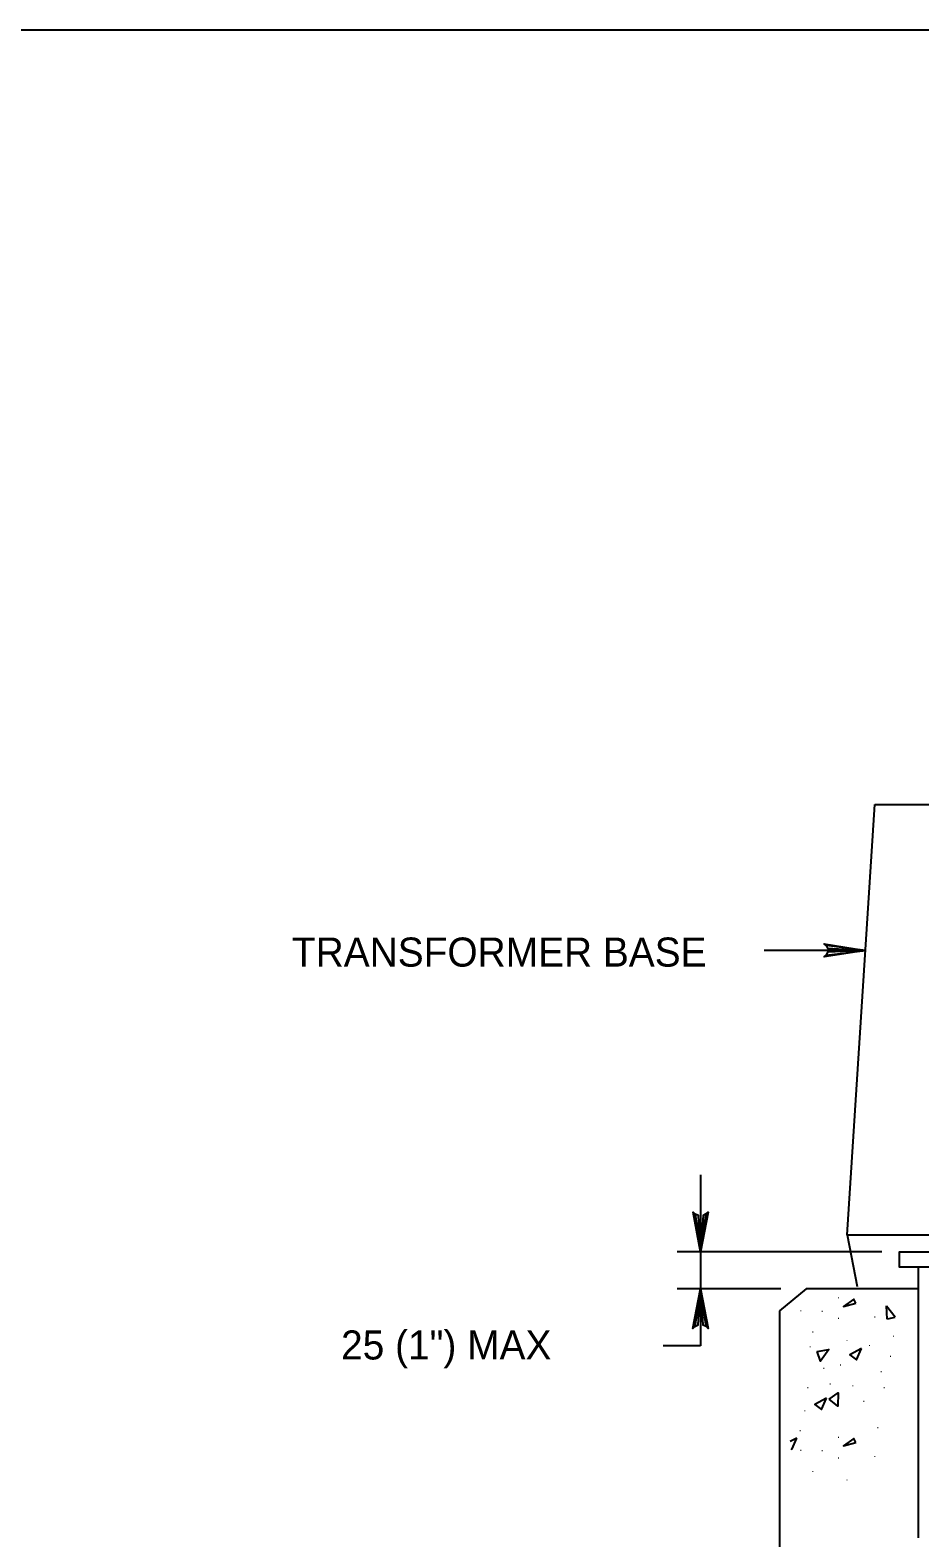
# Model space of a CAD drawing. Extents: x 638448 to 639352, y 297825 to 299013.
# Drawn here: x 638728.3 to 638831.1, y 298230 to 298404.3 of the extents above; entities that cross this region are included whole.
import ezdxf

# ---------------------------------------------------------------- set-up
doc = ezdxf.new("R2010")
doc.units = 0
for name, color, linetype in [('1', 7, 'Continuous'), ('2', 7, 'Continuous'), ('3', 7, 'Continuous')]:
    doc.layers.add(name, color=color, linetype=linetype)

msp = doc.modelspace()

# ---------------------------------------------------------------- linework, layer by layer
at = {"layer": '1'}
msp.add_line((638822.74, 298265.03), (638825.93, 298314.77), dxfattribs=at)
for points in [[(639272.65, 297840.29), (639272.65, 298404.29), (638486.65, 298404.29), (638486.65, 297840.29), (639272.65, 297840.29), (639272.65, 297866.65), (639072.65, 297866.65), (639072.65, 297931.33), (639272.65, 297931.33), (639272.65, 297960.29), (639072.65, 297960.29), (639072.65, 297840.29), (639151.45, 297840.29), (639151.45, 297866.65), (639151.45, 297840.29), (639228.45, 297840.29), (639228.45, 297866.65), (639228.45, 297854.33), (639272.65, 297854.33)], [(638820.31, 298298.48), (638820.48, 298298.15), (638824.85, 298297.91), (638820.31, 298298.48), (638820.08, 298298.68), (638824.85, 298297.91), (638820.48, 298297.69), (638820.32, 298297.37), (638824.85, 298297.91), (638820.08, 298297.15), (638820.32, 298297.37)]]:
    msp.add_lwpolyline(points, dxfattribs=at)
at = {"layer": '2'}
for p, q in [((638825.93, 298314.77), (638878.42, 298314.77)), ((638824.85, 298297.91), (638813.15, 298297.91)), ((638805.8, 298271.96), (638805.8, 298263.07)), ((638822.74, 298265.03), (638823.91, 298259.06)), ((638822.74, 298265.03), (638881.61, 298265.03)), ((638826.76, 298263.07), (638803.08, 298263.07)), ((638805.8, 298263.07), (638805.8, 298258.79)), ((638830.94, 298261.27), (638830.94, 298229.99)), ((638815.05, 298258.79), (638803.08, 298258.79)), ((638817.98, 298258.79), (638814.92, 298256.25)), ((638830.94, 298258.79), (638817.98, 298258.79)), ((638814.92, 298256.25), (638814.92, 298221.59)), ((638805.8, 298252.17), (638801.46, 298252.17))]:
    msp.add_line(p, q, dxfattribs=at)
for points in [[(638806.45, 298267.43), (638806.07, 298267.26), (638805.8, 298263.07), (638806.45, 298267.43), (638806.68, 298267.65), (638805.8, 298263.07), (638805.55, 298267.26), (638805.17, 298267.41), (638805.8, 298263.07), (638804.92, 298267.65), (638805.17, 298267.41)], [(638805.14, 298254.43), (638805.52, 298254.6), (638805.8, 298258.79), (638805.14, 298254.43), (638804.91, 298254.21), (638805.8, 298258.79), (638806.04, 298254.6), (638806.42, 298254.45), (638805.8, 298258.79), (638806.67, 298254.21), (638806.42, 298254.45)], [(638805.8, 298258.79), (638805.8, 298252.17)], [(638827.34, 298255.28), (638827.3, 298256.81)], [(638827.3, 298256.81), (638828.27, 298255.56)], [(638828.26, 298255.45), (638827.34, 298255.28)], [(638816.91, 298241.5), (638816.16, 298241.11)], [(638816.32, 298240.2), (638816.91, 298241.5)], [(638816.21, 298240.28), (638816.32, 298240.2)]]:
    msp.add_lwpolyline(points, dxfattribs=at)
for points in [[(638843.18, 298263.07), (638843.18, 298261.27), (638828.78, 298261.27), (638828.78, 298263.07)], [(638823.73, 298257.14), (638823.49, 298257.6), (638822.31, 298256.75)], [(638819.26, 298251.54), (638820.61, 298251.77), (638819.64, 298250.43)], [(638824.41, 298251.88), (638823.03, 298251.16), (638823.82, 298250.58)], [(638820.36, 298246.13), (638818.98, 298245.41), (638819.76, 298244.82)], [(638820.66, 298246.01), (638821.69, 298246.75), (638821.65, 298245.2)], [(638823.73, 298241.01), (638823.49, 298241.47), (638822.31, 298240.62)]]:
    msp.add_lwpolyline(points, close=True, dxfattribs=at)

# ---------------------------------------------------------------- texts
for p in [(638817.22, 298256.17), (638819.67, 298256.11), (638821.56, 298257.67), (638821.56, 298255.29), (638825.78, 298255.45), (638818.6, 298253.71), (638822.55, 298252.74), (638827.91, 298253.24), (638818.3, 298252.01), (638818.3, 298252.01), (638825.15, 298252.16), (638827.59, 298250.91), (638819.86, 298249.52), (638821.81, 298249.91), (638826.5, 298249.14), (638820.61, 298247.71), (638823.23, 298247.5), (638818.04, 298247.28), (638824.49, 298245.7), (638826.84, 298247.28), (638817.67, 298244.61), (638817.14, 298242.31), (638826.13, 298242.66), (638821.56, 298241.54), (638817.22, 298240.04), (638819.67, 298239.99), (638821.56, 298239.16), (638825.78, 298239.32), (638818.6, 298237.59), (638822.55, 298236.62)]:
    msp.add_text('.', height=0.893, dxfattribs=at).set_placement(p)
at = {"layer": '3'}
for s, p in [('TRANSFORMER BASE', (638758.55, 298296.03)), ('25 (1") MAX', (638764.23, 298250.61))]:
    msp.add_text(s, height=3.36, dxfattribs=at).set_placement(p)

doc.saveas('drawing.dxf')
